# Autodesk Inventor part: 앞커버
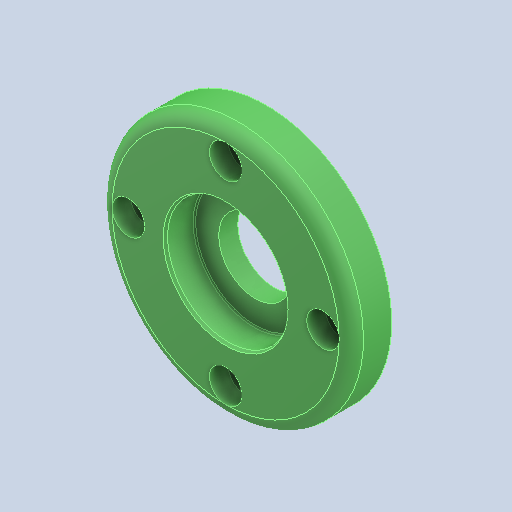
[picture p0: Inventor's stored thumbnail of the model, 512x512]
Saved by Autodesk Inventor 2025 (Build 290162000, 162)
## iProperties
Created: 2025-08
Part Number: 앞커버
Material: 알루미늄 6061
Document SubType Name: Modeling
Designer: infra02
Density: 2.71 g/cm^3
Appearance: 기본값
Author: jhkim
Sending System: Autodesk Inventor 2026
Preprocessor: ST-DEVELOPER v20.1
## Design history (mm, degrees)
feature "솔리드1"
node "솔리드2"
